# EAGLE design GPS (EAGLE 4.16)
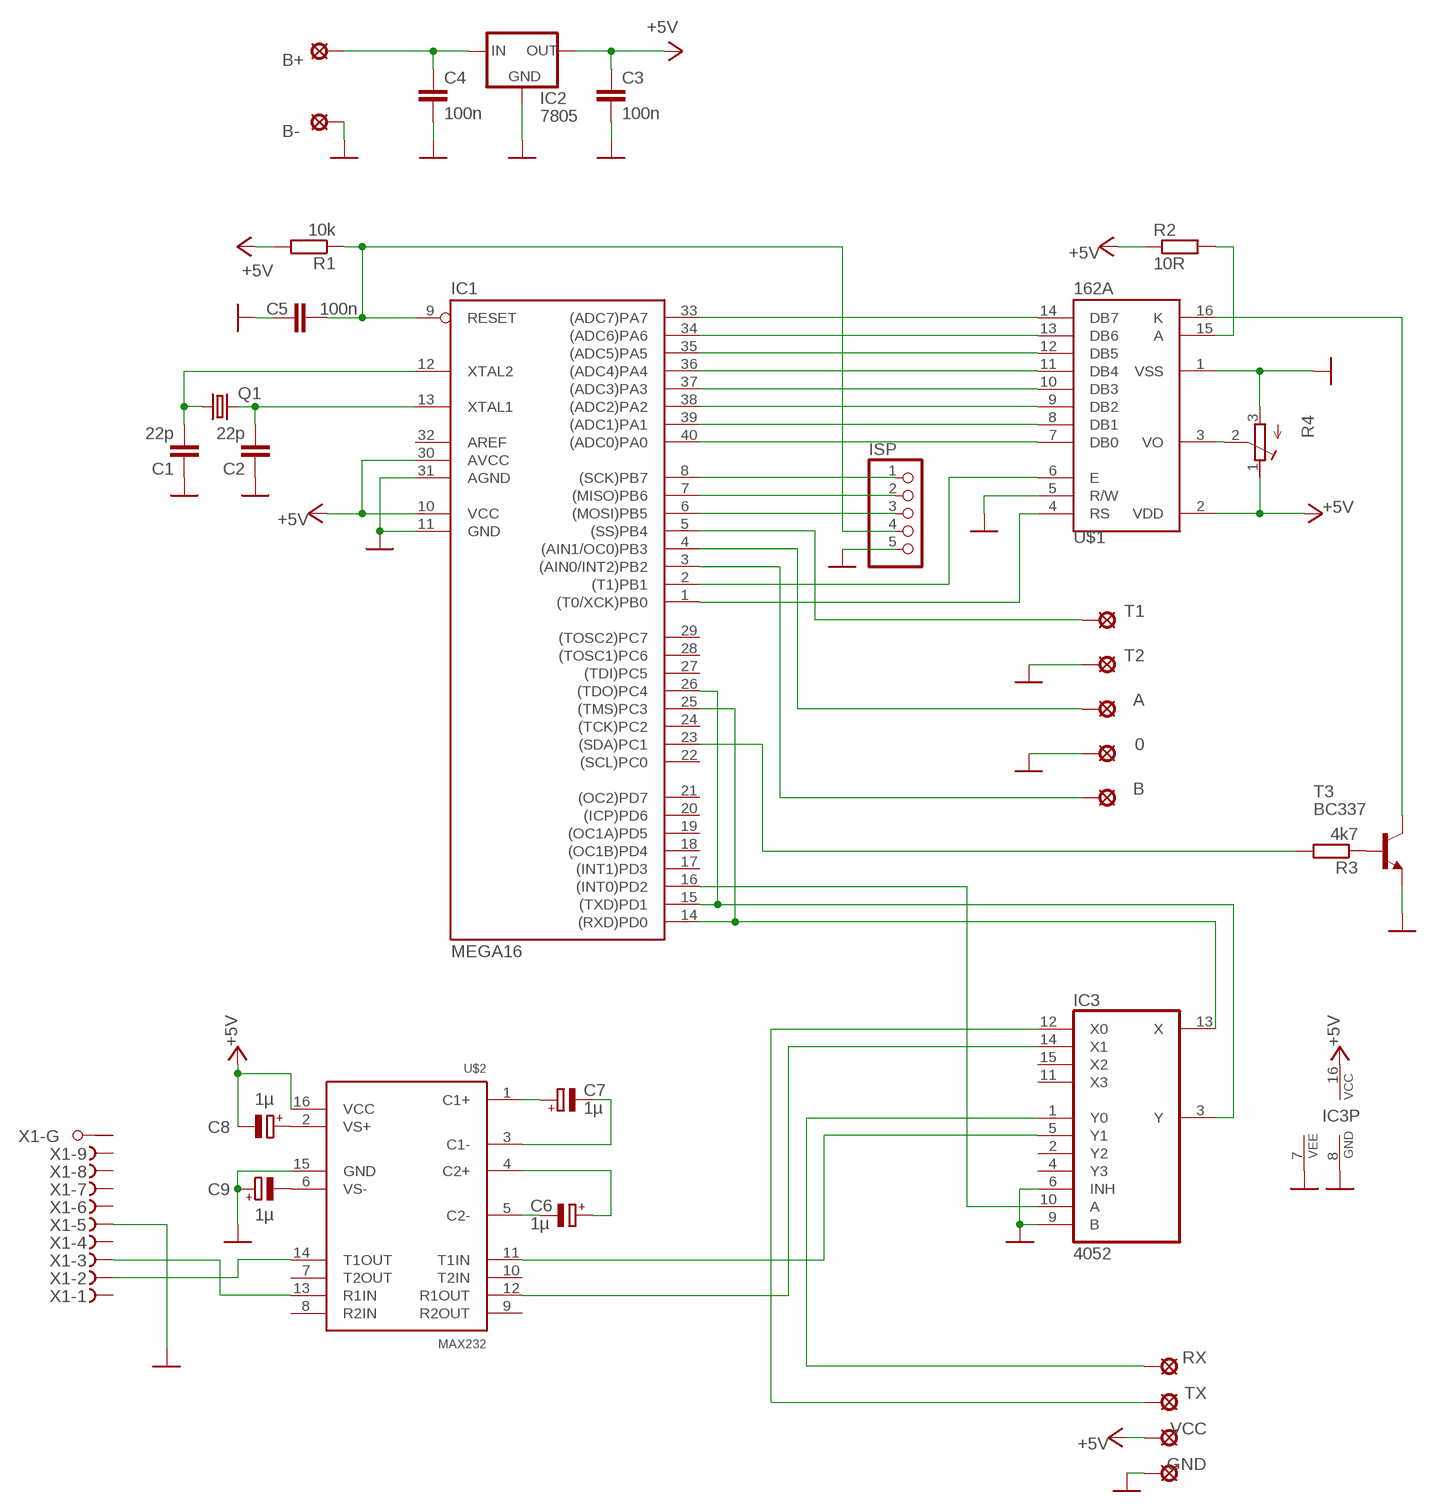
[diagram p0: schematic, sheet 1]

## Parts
0  LSP10  [LSP10]
A  LSP10  [LSP10]
B  LSP10  [LSP10]
B+  LSP10  [LSP10]
B-  LSP10  [LSP10]
C1  22p  C-EU025-024X044  [C025-024X044]
C2  22p  C-EU025-024X044  [C025-024X044]
C3  100n  C-EU025-025X050  [C025-025X050]
C4  100n  C-EU025-025X050  [C025-025X050]
C5  100n  C-EU025-025X050  [C025-025X050]
C6  1µ  CPOL-EUE2.5-5  [E2,5-5]
C7  1µ  CPOL-EUE2.5-5  [E2,5-5]
C8  1µ  CPOL-EUE2.5-5  [E2,5-5]
C9  1µ  CPOL-EUE2.5-5  [E2,5-5]
GND  LSP10  [LSP10]
IC1  MEGA16  MEGA16-P  [DIL40]
IC2  7805  78XXL  [78XXL]
IC3  4052  4052N  [DIL16]
ISP  PINHD-1X5  [1X05]
Q1  CRYTALHC49S  [HC49/S]
R1  10k  R-EU_0207/12  [0207/12]
R2  10R  R-EU_0207/10  [0207/10]
R3  4k7  R-EU_0207/10  [0207/10]
R4  R-TRIMMT93YA  [RTRIMT93YA]
RX  LSP10  [LSP10]
T1  LSP10  [LSP10]
T2  LSP10  [LSP10]
T3  BC337  BC337-16-NPN-TO92-EBC  [TO92-EBC]
TX  LSP10  [LSP10]
U$1  162A  [162A]
U$2  MAX232  MAX232_TI  [DIL16]
VCC  LSP10  [LSP10]
X1  F09HPS  [F09HP]

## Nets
+5V: C3.1 C8.- IC1.10(VCC) IC1.30(AVCC) IC2.OUT IC3.16(VCC) R1.2 R2.1 R4.1(A) U$1.2(VDD) U$2.16(VCC) VCC.MP
GND: 0.MP B-.MP C1.1 C2.1 C3.2 C4.2 C5.1 C9.+ GND.MP IC1.11(GND) IC1.31(AGND) IC2.GND IC3.6(INH) IC3.7(VEE) IC3.8(GND) IC3.9(B) ISP.5 R4.3(E) T2.MP T3.E U$1.1(VSS) U$1.5(R/W) U$2.15(GND) X1.5(-5:F)
N$1: B+.MP C4.1 IC2.IN
N$2: C1.2 IC1.12(XTAL2) Q1.1
N$3: C2.2 IC1.13(XTAL1) Q1.2
N$4: IC1.33((ADC7)PA7) U$1.14(DB7)
N$5: IC1.34((ADC6)PA6) U$1.13(DB6)
N$6: IC1.1((T0/XCK)PB0) U$1.4(RS)
N$7: IC1.2((T1)PB1) U$1.6(E)
N$8: C5.2 IC1.9(RESET) ISP.4 R1.1
N$9: IC1.40((ADC0)PA0) U$1.7(DB0)
N$10: IC1.39((ADC1)PA1) U$1.8(DB1)
N$11: IC1.38((ADC2)PA2) U$1.9(DB2)
N$12: IC1.37((ADC3)PA3) U$1.10(DB3)
N$13: IC1.36((ADC4)PA4) U$1.11(DB4)
N$14: IC1.35((ADC5)PA5) U$1.12(DB5)
N$15: IC1.15((TXD)PD1) IC1.26((TDO)PC4) IC3.3(Y)
N$16: IC3.12(X0) TX.MP
N$17: U$2.14(T1OUT) X1.2(-2:F)
N$18: U$2.13(R1IN) X1.3(-3:F)
N$19: IC3.5(Y1) U$2.11(T1IN)
N$20: IC3.14(X1) U$2.12(R1OUT)
N$21: IC1.14((RXD)PD0) IC1.25((TMS)PC3) IC3.13(X)
N$22: IC3.1(Y0) RX.MP
N$23: IC1.16((INT0)PD2) IC3.10(A)
N$24: IC1.8((SCK)PB7) ISP.1
N$25: IC1.7((MISO)PB6) ISP.2
N$26: IC1.6((MOSI)PB5) ISP.3
N$27: C6.+ U$2.4(C2+)
N$28: C6.- U$2.5(C2-)
N$29: C7.+ U$2.1(C1+)
N$30: C7.- U$2.3(C1-)
N$31: C8.+ U$2.2(VS+)
N$32: C9.- U$2.6(VS-)
N$33: B.MP IC1.3((AIN0/INT2)PB2)
N$34: A.MP IC1.4((AIN1/OC0)PB3)
N$35: IC1.5((SS)PB4) T1.MP
N$36: T3.C U$1.16(K)
N$37: R2.2 U$1.15(A)
N$38: R3.1 T3.B
N$39: IC1.23((SDA)PC1) R3.2
N$40: R4.2(S) U$1.3(VO)
Unconnected: IC1.17((INT1)PD3) IC1.18((OC1B)PD4) IC1.19((OC1A)PD5) IC1.20((ICP)PD6) IC1.21((OC2)PD7) IC1.22((SCL)PC0) IC1.24((TCK)PC2) IC1.27((TDI)PC5) IC1.28((TOSC1)PC6) IC1.29((TOSC2)PC7) IC3.2(Y2) IC3.4(Y3) IC3.11(X3) IC3.15(X2) U$2.7(T2OUT) U$2.8(R2IN) U$2.9(R2OUT) U$2.10(T2IN) X1.1(-1:F) X1.4(-4:F) X1.6(-6:F) X1.7(-7:F) X1.8(-8:F) X1.9(-9:F) X1.G1(-G:G1) X1.G2(-G:G2)

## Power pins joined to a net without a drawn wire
AREF: IC1.32(AREF)

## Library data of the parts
0 A B B+ B- GND RX T1 T2 TX VCC = solpad:LSP10: SOLDER PAD
C1-C5 = rcl:C-EU: CAPACITOR, European symbol
C6-C9 = rcl:CPOL-EU: POLARIZED CAPACITOR, European symbol
IC1 = avr:MEGA16-P: MICROCONTROLLER 16 Kbytes FLASH 1 kbytes SRAM 512 bytes EEPROM USART 8-channel 10 bit ADC
IC2 = v-reg:78XXL: VOLTAGE REGULATOR
IC3 = 40xx:4052: Dual 4-channel ANALOG MULTIPLEXER
ISP = pinhead:PINHD-1X5: PIN HEADER
Q1 = crystal:CRYTAL: CRYSTAL
R1-R3 = rcl:R-EU_: RESISTOR, European symbol
R4 = rcl:R-TRIMM: Trimm resistor
T3 = transistor:*-NPN-: NPN Transistror
U$1 = displaytech_(chr):162A
U$2 = max232ti:MAX232_TI: MAX232, Texas Instruments Version
X1 = con-subd:F09HPS: SUB-D

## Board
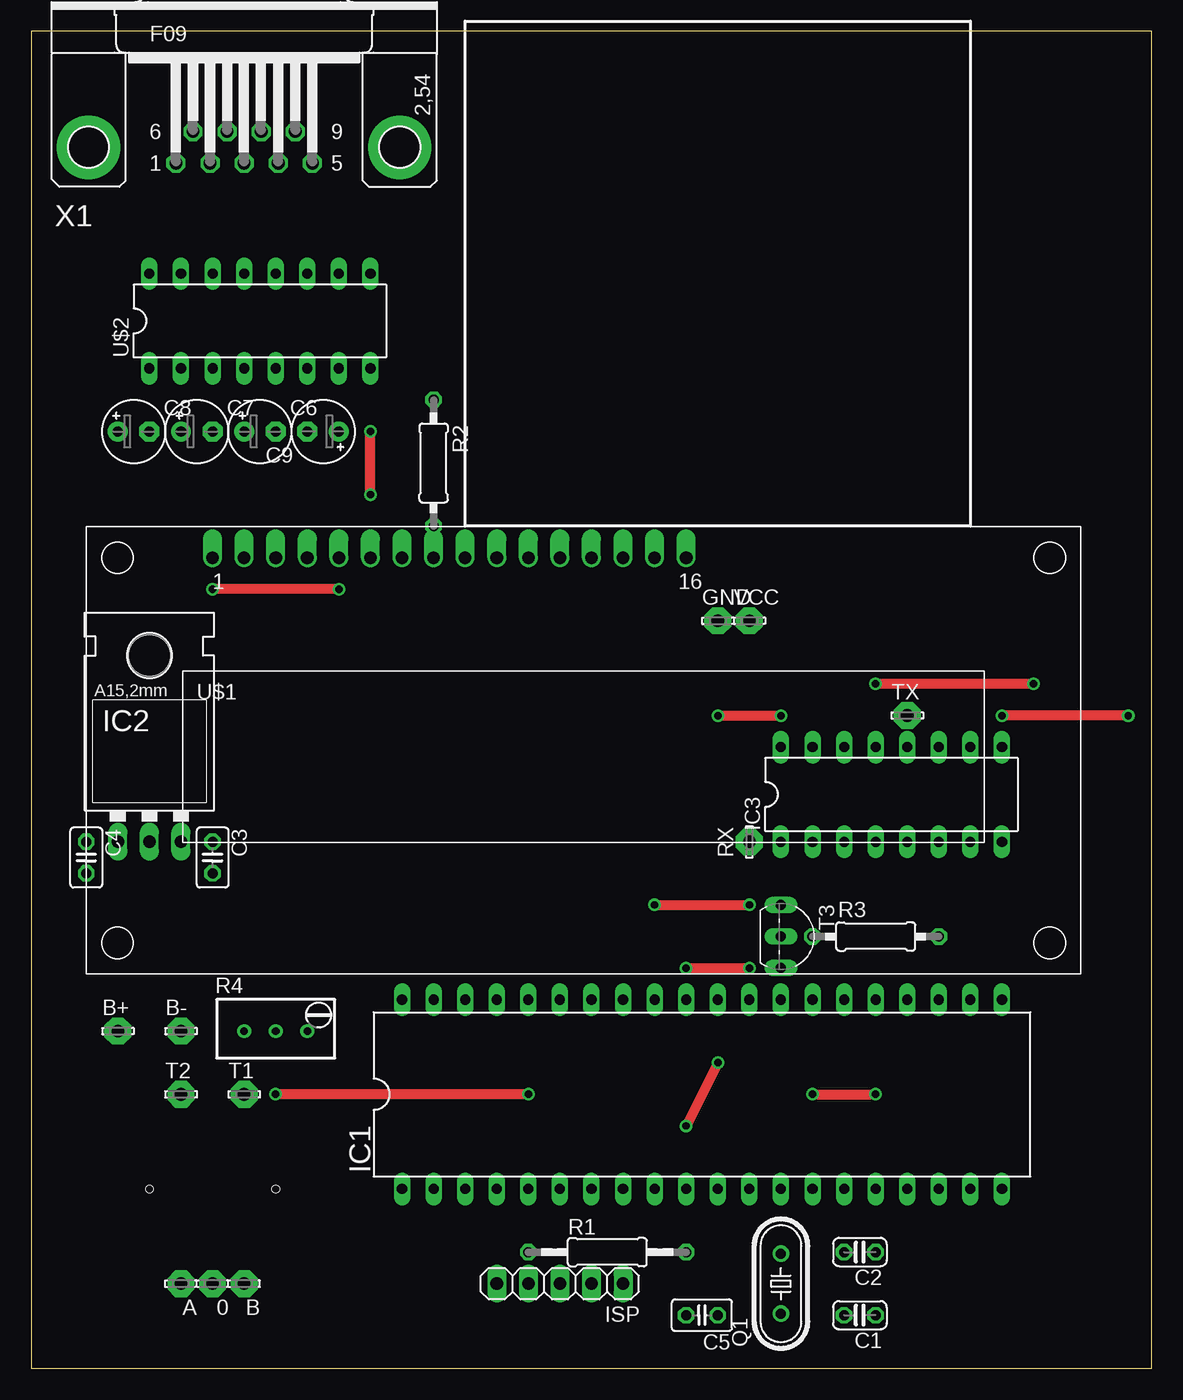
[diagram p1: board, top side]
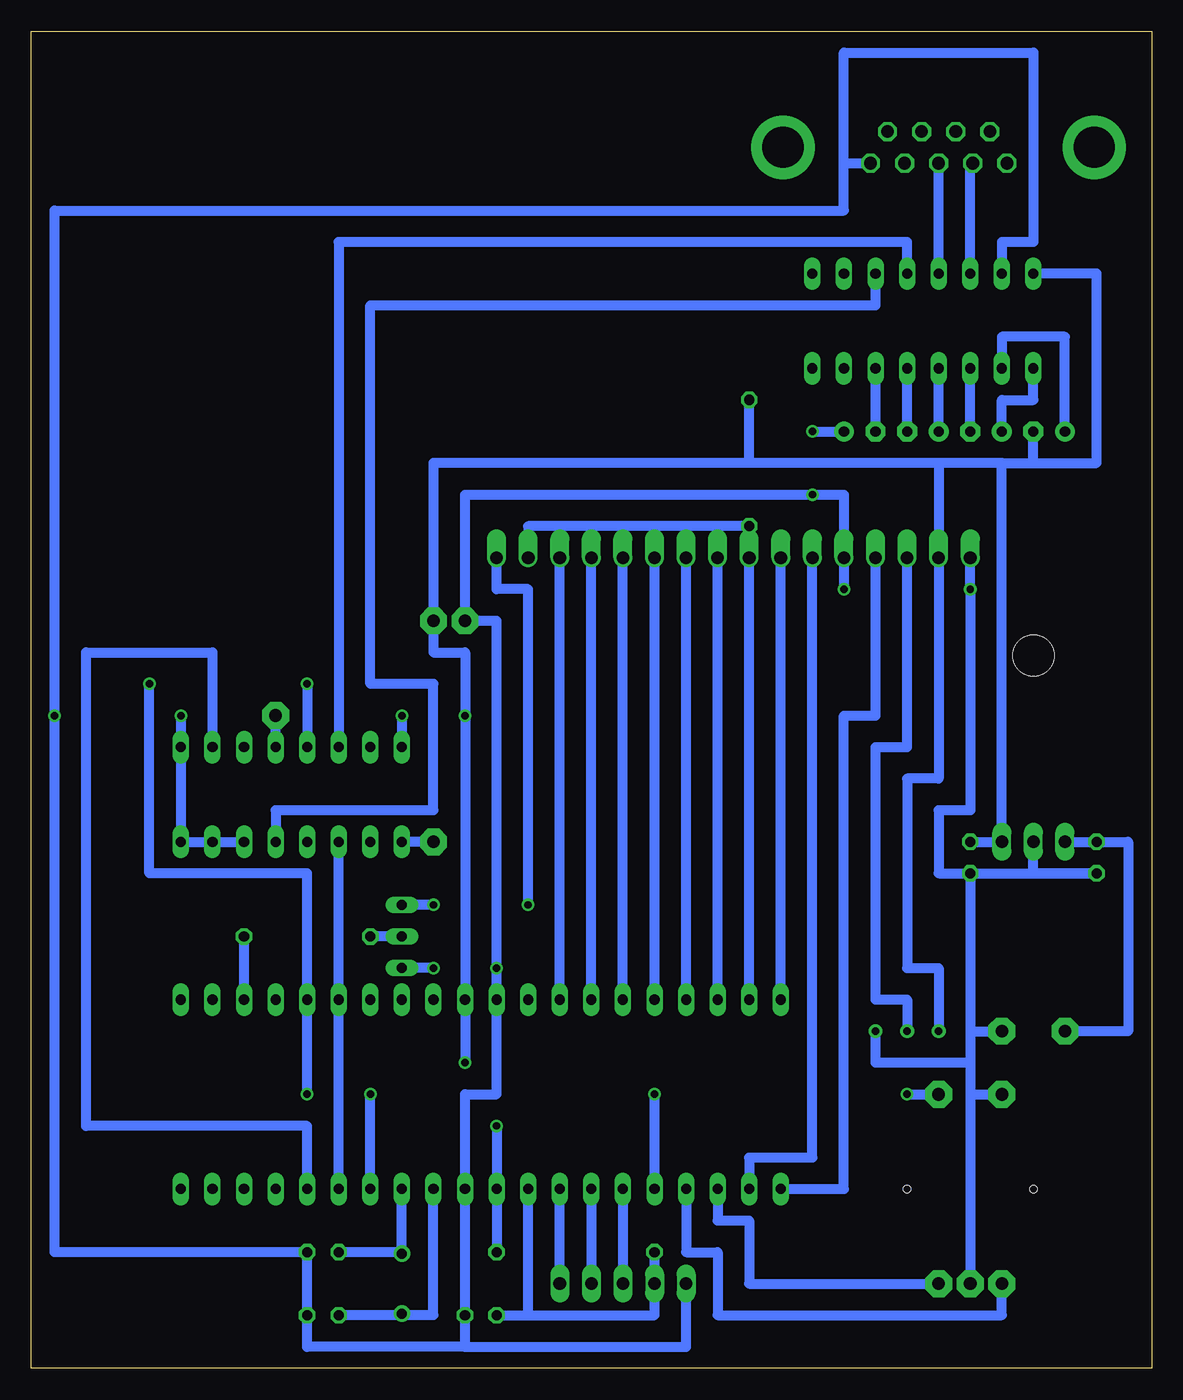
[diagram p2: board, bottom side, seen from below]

Size 90.15 x 107.62 mm. Coordinates in mm from the lower left corner, seen from the top.
Outline: 0,0 90.15,0 90.15,107.62 0,107.62 0,0
Copper layers (1*16): Top 0.035mm / dielectric 1.5mm / Bottom 0.035mm
Design rules "default": minimum track width 10mil, minimum drill 24mil, track to track 8mil, track to pad 8mil, pad to pad 8mil, via to via 8mil, smd to smd 8mil, copper to edge 40mil, drill to drill 8mil, minimum pad ring 10mil, minimum via ring 8mil, stop-mask expansion 4mil, vias tented up to drill 0mil, thermal gap 10mil
Holes 0.6 mm at 9.52,14.44 19.68,14.44

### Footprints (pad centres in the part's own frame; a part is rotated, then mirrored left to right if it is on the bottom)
LSP10 = drill 1.016 pad 2.159 octagon: MP 0,0
C025-024X044 = drill 0.813 octagon: 1 -1.27,0; 2 1.27,0
C025-025X050 = drill 0.813 octagon: 1 -1.27,0; 2 1.27,0
E2,5-5 = drill 0.813 pad 1.6 round: + -1.27,0 | drill 0.813 pad 1.6 octagon: - 1.27,0
DIL40 = drill 0.813 long: 1 -24.13,-7.62; 2 -21.59,-7.62; 3 -19.05,-7.62; 4 -16.51,-7.62; 5 -13.97,-7.62; 6 -11.43,-7.62; 7 -8.89,-7.62; 8 -6.35,-7.62; 9 -3.81,-7.62; 10 -1.27,-7.62; 11 1.27,-7.62; 12 3.81,-7.62; 13 6.35,-7.62; 14 8.89,-7.62; 15 11.43,-7.62; 16 13.97,-7.62; 17 16.51,-7.62; 18 19.05,-7.62; 19 21.59,-7.62; 20 24.13,-7.62; 21 24.13,7.62; 22 21.59,7.62; 23 19.05,7.62; 24 16.51,7.62; 25 13.97,7.62; 26 11.43,7.62; 27 8.89,7.62; 28 6.35,7.62; 29 3.81,7.62; 30 1.27,7.62; 31 -1.27,7.62; 32 -3.81,7.62; 33 -6.35,7.62; 34 -8.89,7.62; 35 -11.43,7.62; 36 -13.97,7.62; 37 -16.51,7.62; 38 -19.05,7.62; 39 -21.59,7.62; 40 -24.13,7.62
78XXL = drill 1.016 long: GND 0,-3.81; IN -2.54,-3.81; OUT 2.54,-3.81 | hole 3.302: 0,11.176
DIL16 = drill 0.813 long: 1 -8.89,-3.81; 2 -6.35,-3.81; 3 -3.81,-3.81; 4 -1.27,-3.81; 5 1.27,-3.81; 6 3.81,-3.81; 7 6.35,-3.81; 8 8.89,-3.81; 9 8.89,3.81; 10 6.35,3.81; 11 3.81,3.81; 12 1.27,3.81; 13 -1.27,3.81; 14 -3.81,3.81; 15 -6.35,3.81; 16 -8.89,3.81
1X05 = drill 1.016 long: 1 -5.08,0; 2 -2.54,0; 3 0,0; 4 2.54,0; 5 5.08,0
HC49/S = drill 0.813 round: 1 -2.413,0; 2 2.413,0
0207/12 = drill 0.813 octagon: 1 -6.35,0; 2 6.35,0
0207/10 = drill 0.813 octagon: 1 -5.08,0; 2 5.08,0
RTRIMT93YA = drill 0.61 round: 1 0,-2.54; 2 0,0; 3 0,2.54
TO92-EBC = drill 0.813 long: B 0,-1.27; C -2.54,-1.27; E 2.54,-1.27
162A = drill 1.016 offset: 1 0,0; 2 2.54,0; 3 5.08,0; 4 7.62,0; 5 10.16,0; 6 12.7,0; 7 15.24,0; 8 17.78,0; 9 20.32,0; 10 22.86,0; 11 25.4,0; 12 27.94,0; 13 30.48,0; 14 33.02,0; 15 35.56,0; 16 38.1,0
F09HP = drill 1.016 octagon: 1 -5.486,-1.27; 2 -2.743,-1.27; 3 0,-1.27; 4 2.743,-1.27; 5 5.486,-1.27; 6 -4.115,1.27; 7 -1.372,1.27; 8 1.372,1.27; 9 4.115,1.27 | drill 3.302 pad 5.08 round: G1 -12.522,0; G2 12.522,0

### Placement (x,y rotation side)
0  14.6,6.82 180 top
A  12.06,6.82 180 top
B  17.14,6.82 180 top
B+  6.98,27.14 0 top
B-  12.06,27.14 0 top
C1  66.67,4.28 180 top
C2  66.67,9.36 180 top
C3  14.6,41.11 270 top
C4  4.44,41.11 270 top
C5  53.97,4.28 180 top
C6  18.41,75.4 0 top
C7  13.33,75.4 0 top
C8  8.25,75.4 0 top
C9  23.49,75.4 180 top
GND  55.24,60.16 0 top
IC1  53.97,22.06 0 top
IC2  9.52,46.19 0 top
IC3  69.21,46.19 0 top
ISP  42.54,6.82 180 top
Q1  60.32,6.82 90 top
R1  46.35,9.36 0 top
R2  32.38,72.86 270 top
R3  67.94,34.76 0 top
R4  19.68,27.14 270 top
RX  57.78,42.38 90 top
T1  17.14,22.06 0 top
T2  12.06,22.06 0 top
T3  61.59,34.76 270 top
TX  70.48,52.54 0 top
U$1  14.6,65.24 0 top
U$2  18.41,84.29 0 top
VCC  57.78,60.16 0 top
X1  17.14,98.26 0 top

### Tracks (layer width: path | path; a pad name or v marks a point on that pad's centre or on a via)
+5V  (via drill 0.6)
  Top 0.813: v55.24,24.6 v52.7,19.52 | v55.24,52.54 v60.32,52.54
  Bottom 0.813: 17.14,72.86 32.38,72.86 | 32.38,72.86 57.78,72.86 VCC.MP 57.78,57.62 55.24,57.62 v55.24,52.54 IC1.30 v55.24,24.6 | 17.14,72.86 U$1.2 17.14,47.46 19.68,47.46 19.68,32.22 17.14,32.22 R4.1 | 12.06,72.86 17.14,72.86 | 12.06,72.86 IC2.OUT C3.1 | v52.7,19.52 IC1.10 R1.2 | v60.32,52.54 IC3.16 | 12.06,72.86 9.52,72.86 | 9.52,72.86 C8.- | 9.52,72.86 4.44,72.86 4.44,88.1 U$2.16 | 32.38,72.86 R2.1
GND  (via drill 0.6)
  Top 0.813: v24.76,62.7 v14.6,62.7 | v88.26,52.54 v78.1,52.54 | v27.3,70.32 v27.3,75.4 | v52.7,32.22 v57.78,32.22
  Bottom 0.813: C1.1 C2.1 | IC1.11 55.24,22.06 52.7,22.06 IC1.31 v52.7,32.22 52.7,60.16 GND.MP 55.24,70.32 28.57,70.32 | U$1.1 v14.6,62.7 14.6,44.92 17.14,44.92 17.14,39.84 C3.2 | IC2.GND 9.52,39.84 C4.2 C3.2 | v24.76,62.7 U$1.5 24.76,70.32 28.57,70.32 | 55.24,1.74 67.94,1.74 C1.1 | 55.24,1.74 C5.1 | C5.1 IC1.11 | C1.1 C2.1 | C2.1 88.26,9.36 v88.26,52.54 88.26,93.18 24.76,93.18 24.76,96.99 | 24.76,96.99 X1.5 | 24.76,96.99 24.76,105.88 9.52,105.88 9.52,90.64 12.06,90.64 U$2.15 | ISP.5 37.46,1.74 55.24,1.74 | C5.1 IC1.11 | IC3.8 IC3.7 | IC3.8 IC3.9 v78.1,52.54 | IC3.8 IC3.6 | v27.3,75.4 C9.+ | 28.57,70.32 v27.3,70.32 | C3.2 14.6,27.14 | 14.6,27.14 14.6,24.6 | v57.78,32.22 T3.E | 14.6,24.6 14.6,22.06 | 14.6,22.06 0.MP | R4.3 22.22,24.6 14.6,24.6 | 14.6,27.14 B-.MP | 14.6,22.06 T2.MP
N$1
  Bottom 0.813: C4.1 IC2.IN C4.1 | B+.MP 1.9,27.14 1.9,42.38 C4.1
N$2
  Bottom 0.813: 60.32,4.28 C1.2 | IC1.12 57.78,4.28 60.32,4.28 | 60.32,4.28 Q1.1
N$3
  Bottom 0.813: 60.32,9.36 IC1.13 | Q1.2 60.32,9.36 | 60.32,9.36 C2.2
N$4
  Bottom 0.813: IC1.33 U$1.14
N$5
  Bottom 0.813: IC1.34 U$1.13
N$6
  Bottom 0.813: U$1.4 22.22,52.54 24.76,52.54 24.76,14.44 IC1.1
N$7
  Bottom 0.813: IC1.2 32.38,16.98 27.3,16.98 U$1.6
N$8
  Bottom 0.813: ISP.4 40,4.28 50.16,4.28 | ISP.4 R1.1 ISP.4 | C5.2 50.16,4.28 | 50.16,4.28 IC1.9
N$9
  Bottom 0.813: IC1.40 U$1.7
N$10
  Bottom 0.813: IC1.39 U$1.8
N$11
  Bottom 0.813: IC1.38 U$1.9
N$12
  Bottom 0.813: IC1.37 U$1.10
N$13
  Bottom 0.813: IC1.36 U$1.11
N$14
  Bottom 0.813: IC1.35 U$1.12
N$15
  Bottom 0.813: IC1.15 IC1.26 IC3.3
N$16
  Bottom 0.813: IC3.12 TX.MP
N$17
  Bottom 0.813: X1.2 14.6,96.99 U$2.14
N$18
  Bottom 0.813: U$2.13 X1.3
N$19
  Bottom 0.813: U$2.11 22.22,85.56 62.86,85.56 62.86,55.08 57.78,55.08 57.78,44.92 70.48,44.92 IC3.5
N$20
  Bottom 0.813: U$2.12 19.68,90.64 65.4,90.64 IC3.14
N$21  (via drill 0.6)
  Top 0.813: v62.86,22.06 v67.94,22.06 | v80.64,55.08 v67.94,55.08
  Bottom 0.813: IC1.14 v62.86,22.06 | v67.94,55.08 IC3.13 | v67.94,22.06 IC1.25 67.94,39.84 80.64,39.84 v80.64,55.08
N$22
  Bottom 0.813: RX.MP IC3.1
N$23
  Bottom 0.813: IC1.16 67.94,19.52 85.72,19.52 85.72,57.62 75.56,57.62 IC3.10
N$24
  Bottom 0.813: ISP.1 IC1.8
N$25
  Bottom 0.813: IC1.7 ISP.2
N$26
  Bottom 0.813: IC1.6 ISP.3
N$27
  Bottom 0.813: C6.+ U$2.4
N$28
  Bottom 0.813: C6.- U$2.5
N$29
  Bottom 0.813: C7.+ 12.06,77.94 9.52,77.94 U$2.1
N$30
  Bottom 0.813: C7.- U$2.3
N$31
  Bottom 0.813: C8.+ 6.98,83.02 12.06,83.02 U$2.2
N$32
  Bottom 0.813: C9.- U$2.6
N$33
  Bottom 0.813: IC1.3 34.92,11.9 32.38,11.9 32.38,6.82 B.MP
N$34
  Bottom 0.813: A.MP 12.06,4.28 34.92,4.28 34.92,9.36 37.46,9.36 IC1.4
N$35  (via drill 0.6)
  Top 0.813: v40,22.06 v19.68,22.06
  Bottom 0.813: IC1.5 v40,22.06 | v19.68,22.06 T1.MP v19.68,22.06
N$36  (via drill 0.6)
  Top 0.813: v50.16,37.3 v57.78,37.3
  Bottom 0.813: v57.78,37.3 T3.C | v50.16,37.3 50.16,62.7 52.7,62.7 U$1.16
N$37
  Bottom 0.813: R2.2 50.16,67.78 U$1.15
N$38
  Bottom 0.813: T3.B R3.1
N$39
  Bottom 0.813: IC1.23 R3.2
N$40
  Bottom 0.813: R4.2 19.68,29.68 22.22,29.68 22.22,50 19.68,50 U$1.3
